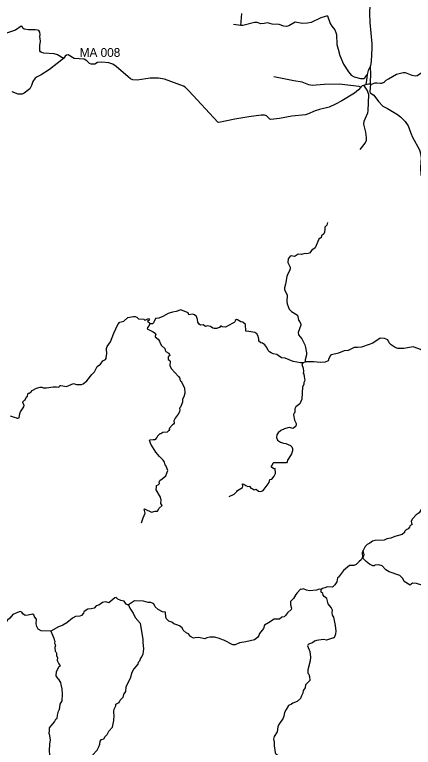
# Model space of a CAD drawing. Extents: x 332 to 501, y 9447 to 9559.
# Drawn here: x 458.02 to 475.23, y 9479.97 to 9511.64 of the extents above; entities that cross this region are included whole.
import ezdxf

# ---------------------------------------------------------------- set-up
doc = ezdxf.new("R2010")
doc.units = 0
for name, color, linetype in [('Level 31', 7, 'Continuous'), ('Level 4', 7, 'Continuous'), ('Level 5', 7, 'Continuous'), ('Level 6', 7, 'Continuous'), ('Level 7', 7, 'Continuous'), ('Level 8', 7, 'Continuous')]:
    doc.layers.add(name, color=color, linetype=linetype)

msp = doc.modelspace()

# ---------------------------------------------------------------- linework, layer by layer
at = {"layer": 'Level 4'}
for points in [[(473.3815, 9512.9204), (473.3415, 9511.6756), (473.3582, 9511.3032)], [(473.3582, 9511.3032), (473.4387, 9510.3831)], [(473.4387, 9510.3831), (473.445, 9510.1938), (473.4148, 9509.636)], [(462.2592, 9509.5019), (462.0871, 9509.5596), (461.7829, 9509.5879), (461.5917, 9509.569), (461.4851, 9509.5084), (461.3204, 9509.4996), (461.2528, 9509.5324), (461.1354, 9509.6523), (461.0181, 9509.723), (460.594, 9509.752), (460.3265, 9509.906), (460.262, 9509.8946), (460.2055, 9509.8444)], [(473.4148, 9509.636), (473.3907, 9509.429)], [(467.5283, 9507.1277), (466.8391, 9506.9741), (466.7923, 9506.9924), (465.537, 9508.3514), (465.38, 9508.5076), (465.3055, 9508.5517), (464.4927, 9508.8496), (464.2264, 9508.9039), (463.8642, 9508.8912), (463.3101, 9508.8105), (463.1144, 9508.8218), (463.0261, 9508.8661), (462.915, 9508.9544), (462.4064, 9509.4037), (462.2592, 9509.5019)], [(473.3907, 9509.429), (473.2771, 9509.2289)], [(472.9707, 9508.5154), (472.8695, 9508.394), (472.6877, 9508.2489), (472.1475, 9507.9119), (471.8794, 9507.7667), (471.6035, 9507.648), (471.1826, 9507.5484), (470.9939, 9507.4853), (470.6646, 9507.3435)], [(473.0437, 9508.5744), (472.9707, 9508.5154)], [(473.355, 9508.3214), (473.3744, 9508.257), (473.5233, 9508.1598), (473.7252, 9507.8866), (473.9208, 9507.6878), (474.124, 9507.5913), (474.5461, 9507.3199)], [(470.6646, 9507.3435), (470.5736, 9507.3155), (469.989, 9507.2491), (469.4542, 9507.1558), (469.0831, 9507.1104), (469.0376, 9507.1243), (468.8912, 9507.2695), (468.8055, 9507.3022), (468.6672, 9507.2997), (468.1245, 9507.231), (467.5283, 9507.1277)], [(474.5461, 9507.3199), (474.6869, 9507.2208), (474.8763, 9507.0284), (475.005, 9506.8365), (475.1276, 9506.5158)], [(475.1276, 9506.5158), (475.1968, 9506.3519), (475.4947, 9505.794), (475.5502, 9505.6451), (475.5755, 9505.4482), (475.5452, 9505.0342), (475.557, 9504.6897)], [(465.7046, 9498.6925), (465.5401, 9498.6668), (465.5144, 9498.7491), (465.1957, 9498.8878), (464.9952, 9498.8159), (464.8359, 9498.7902), (464.6457, 9498.7285), (464.4195, 9498.5948), (464.243, 9498.5262)], [(464.243, 9498.5262), (464.0956, 9498.5126), (464.0134, 9498.3224)], [(465.7817, 9498.6668), (465.7046, 9498.6925)], [(465.8691, 9498.5897), (465.7817, 9498.6668)], [(465.9976, 9498.2556), (465.9308, 9498.3532), (465.9205, 9498.4612), (465.8691, 9498.5897)], [(463.8547, 9498.2938), (463.7599, 9498.3741)], [(464, 9498.309), (463.9723, 9498.2813), (463.8695, 9498.2813), (463.8547, 9498.2938)], [(464.0134, 9498.3224), (464, 9498.309)], [(466.0491, 9498.2247), (465.9976, 9498.2556)], [(466.1519, 9498.235), (466.0491, 9498.2247)], [(466.8646, 9498.12), (466.7327, 9498.0756), (466.6402, 9498.0756), (466.5734, 9498.0911), (466.4757, 9498.1579), (466.4089, 9498.1785), (466.3472, 9498.1887), (466.2547, 9498.1682), (466.1519, 9498.235)], [(468.0013, 9497.9625), (467.9821, 9498.2438), (467.8734, 9498.3526), (467.7796, 9498.3714), (467.6371, 9498.4577), (467.6034, 9498.4614), (467.5359, 9498.4239), (467.5246, 9498.3601), (467.4984, 9498.3376), (467.4346, 9498.3151), (467.1234, 9498.135), (466.9846, 9498.1426), (466.9396, 9498.1801), (466.9021, 9498.1801), (466.8935, 9498.1672)], [(466.8935, 9498.1672), (466.8646, 9498.12)], [(469.0907, 9497.031), (469.026, 9497.0634), (468.9585, 9497.1309), (468.9135, 9497.2584), (468.8197, 9497.3784), (468.7185, 9497.4496), (468.651, 9497.4609), (468.561, 9497.5284), (468.561, 9497.6221), (468.531, 9497.7534), (468.4808, 9497.8425), (468.3871, 9497.8987), (468.1358, 9497.955), (468.0013, 9497.9625)], [(475.9999, 9496.9153), (475.8325, 9496.9871), (475.5416, 9497.175), (475.2766, 9497.2707), (475.2213, 9497.2781), (474.8211, 9497.2098), (474.5634, 9497.2098), (474.453, 9497.254), (474.2763, 9497.3718), (474.1916, 9497.4639), (474.129, 9497.5818), (473.9965, 9497.6518), (473.8087, 9497.6665), (473.4811, 9497.4455), (473.3319, 9497.3866), (472.9896, 9497.2761), (472.8165, 9497.254), (472.6803, 9497.2577), (472.4226, 9497.125), (472.2496, 9497.1066), (471.9999, 9497.0062)], [(469.1797, 9496.9884), (469.0907, 9497.031)], [(469.3425, 9496.961), (469.1797, 9496.9884)], [(469.4, 9496.9035), (469.3425, 9496.961)], [(471.9999, 9497.0062), (471.7047, 9496.9372), (471.6605, 9496.9077), (471.5869, 9496.7825), (471.5565, 9496.684)], [(469.5396, 9496.8131), (469.4, 9496.9035)], [(470.46, 9496.5995), (470.3607, 9496.5995), (470.0491, 9496.6488), (469.6958, 9496.7967), (469.5396, 9496.8131)], [(470.5662, 9496.6271), (470.46, 9496.5995)], [(470.5829, 9496.6314), (470.5662, 9496.6271)], [(471.5565, 9496.684), (471.4325, 9496.6251), (471.229, 9496.6065), (470.9366, 9496.6324), (470.5829, 9496.6314)]]:
    msp.add_lwpolyline(points, dxfattribs=at)
at = {"layer": 'Level 5'}
for points in [[(474.888, 9509.1414), (475.1766, 9509.0213), (475.3212, 9509.0005), (475.4064, 9509.0187), (475.7749, 9509.2648), (475.8733, 9509.3482), (476.1712, 9509.6612), (476.2267, 9509.7483), (476.2886, 9509.7962), (476.4515, 9509.8555), (476.7821, 9509.8908), (476.9537, 9509.9754), (477.1493, 9510.1534), (477.4169, 9510.515), (477.4926, 9510.5844), (477.7609, 9510.6771), (477.9596, 9510.8167), (478.2455, 9511.0621), (478.3169, 9511.0937)], [(460.1202, 9509.7546), (460.0539, 9509.6848), (459.5175, 9509.2754), (459.1645, 9509.0426), (458.9889, 9508.9622), (458.9061, 9508.9029), (458.7984, 9508.7529), (458.7515, 9508.5757), (458.6781, 9508.4305), (458.4236, 9508.2431), (458.3377, 9508.2033), (458.1691, 9508.2095), (457.9068, 9508.3055)], [(460.2055, 9509.8444), (460.1202, 9509.7546)], [(474.0631, 9508.804), (474.1581, 9508.8717), (474.5078, 9509.0654), (474.7949, 9509.1412), (474.888, 9509.1414)], [(473.8211, 9508.6842), (473.8794, 9508.685)], [(473.8794, 9508.685), (473.9382, 9508.7062)], [(473.9382, 9508.7062), (473.94, 9508.7071)], [(473.94, 9508.7071), (473.9856, 9508.7305)], [(473.9856, 9508.7305), (473.9914, 9508.735)], [(473.9914, 9508.735), (474.0538, 9508.7974)], [(474.0538, 9508.7974), (474.0631, 9508.804)], [(471.5245, 9502.6652), (471.5193, 9502.599)], [(471.5193, 9502.599), (471.4983, 9502.5472), (471.4097, 9502.463), (471.4145, 9502.3723), (471.3949, 9502.246), (471.3687, 9502.1712), (471.27, 9502.09), (471.2527, 9502.0052)], [(471.2527, 9502.0052), (471.1504, 9501.9357), (471.0017, 9501.5639), (470.8572, 9501.4601), (470.7549, 9501.3302), (470.6293, 9501.31), (470.5424, 9501.3159), (470.4103, 9501.2779), (470.2616, 9501.2974), (470.1384, 9501.2036), (470.0878, 9501.187), (469.9771, 9501.2137), (469.9176, 9501.2071), (469.8284, 9501.092), (469.8178, 9500.9331), (469.9226, 9500.7215), (469.919, 9500.6574), (469.8893, 9500.5714), (469.8233, 9500.4629), (469.7769, 9500.3229), (469.7151, 9499.9879), (469.667, 9499.8408), (469.6718, 9499.7637), (469.7879, 9499.5141), (469.7767, 9499.2449), (469.7916, 9499.1406), (469.8762, 9498.9087), (469.9727, 9498.8056), (470.2381, 9498.6468), (470.2775, 9498.4369), (470.3376, 9498.3657), (470.374, 9498.2679), (470.3751, 9498.2223), (470.2676, 9497.9014), (470.2688, 9497.8036), (470.423, 9497.6269), (470.5451, 9497.3661), (470.5719, 9497.2629), (470.6243, 9497.0204), (470.6196, 9496.9439), (470.5572, 9496.7186), (470.5614, 9496.6527)], [(461.9876, 9496.9343), (462.0042, 9496.9705), (461.9887, 9497.2136), (462.0071, 9497.305), (462.1551, 9497.5001), (462.296, 9497.8773), (462.475, 9498.2468), (462.5606, 9498.3518), (462.7349, 9498.3982), (462.8997, 9498.553), (463.1478, 9498.6023), (463.2151, 9498.5994), (463.3008, 9498.5621), (463.3728, 9498.4993), (463.6007, 9498.4739), (463.64, 9498.4436), (463.6763, 9498.4454), (463.7995, 9498.5048), (463.8346, 9498.4473), (463.7599, 9498.3741)], [(463.8547, 9498.2938), (463.8283, 9498.2093), (463.7615, 9498.1219), (463.7461, 9498.0602), (464, 9497.9287)], [(464, 9497.9287), (464.1008, 9497.8597), (464.1213, 9497.8289), (464.0802, 9497.7518), (464.0854, 9497.7158), (464.2087, 9497.6233), (464.2704, 9497.5307), (464.2807, 9497.4691), (464.3527, 9497.3457), (464.4966, 9497.212), (464.512, 9497.1349), (464.5429, 9497.0887), (464.6765, 9497.0064), (464.7125, 9496.9139), (464.6508, 9496.8522), (464.6508, 9496.7442), (464.7177, 9496.698), (464.7382, 9496.6494), (464.7228, 9496.4849), (464.7742, 9496.346), (465.0928, 9496)], [(461.8312, 9496.6745), (461.9413, 9496.7422), (461.9722, 9496.7831), (461.9876, 9496.9343)], [(458.1563, 9494.1973), (458.2187, 9494.2137), (458.2364, 9494.4052), (458.2655, 9494.4704), (458.4184, 9494.6929), (458.4219, 9494.7634), (458.3689, 9494.8583), (458.3701, 9494.9034), (458.4373, 9494.974), (458.4605, 9494.9728), (458.5348, 9495.1187), (458.577, 9495.1324), (458.5865, 9495.2593), (458.6097, 9495.2866), (458.643, 9495.2842), (458.7257, 9495.3346), (458.7768, 9495.4041), (458.9565, 9495.4972), (459.1153, 9495.5459), (459.1903, 9495.5448), (459.254, 9495.5128), (459.3962, 9495.5075), (459.6836, 9495.5551), (459.8306, 9495.5599), (459.9026, 9495.5463), (459.9335, 9495.5624), (459.9686, 9495.6122), (460.0186, 9495.6199), (460.2501, 9495.5673), (460.56, 9495.7044), (460.685, 9495.6511), (460.904, 9495.6577), (460.9754, 9495.6892), (461.133, 9495.8168), (461.3483, 9496.0908), (461.4673, 9496.1988), (461.579, 9496.4402), (461.7277, 9496.534), (461.8312, 9496.6745)], [(470.5614, 9496.6527), (470.5662, 9496.6271)], [(465.0928, 9496), (465.1546, 9495.9244), (465.1443, 9495.8781), (465.1752, 9495.8164), (465.2163, 9495.7804), (465.2317, 9495.7238), (465.3499, 9495.5078), (465.3602, 9495.2764), (465.3294, 9495.1222), (465.2625, 9495.0215), (465.2677, 9494.8878), (465.1803, 9494.6821), (465.134, 9494.6307), (465.1443, 9494.5587), (465.134, 9494.4815), (465.0844, 9494.3794)], [(470.5134, 9496), (470.5514, 9495.8288), (470.5111, 9495.7431), (470.5027, 9495.6507), (470.4422, 9495.5532), (470.4187, 9495.0253), (470.3348, 9494.8278), (470.1551, 9494.6901), (470.1199, 9494.6027), (470.1215, 9494.4481), (470.0695, 9494.3967), (470.0594, 9494.353), (470.1081, 9494.1161), (470.1769, 9493.9758), (470.1769, 9493.917), (470.1534, 9493.8548), (470.0426, 9493.7607), (469.8797, 9493.7926), (469.8092, 9493.7792)], [(458.1151, 9494.2023), (458.0098, 9494.2242), (457.8385, 9494.2894)], [(458.1151, 9494.2023), (458.1563, 9494.1973)], [(465.0826, 9494.3735), (464.949, 9494.2055), (464.8976, 9494.0821), (464.9079, 9493.9895), (464.877, 9493.9381), (464.8307, 9493.9134), (464.6971, 9493.7592), (464.7022, 9493.718), (464.6765, 9493.6666), (464.5994, 9493.5946), (464.4195, 9493.5895), (464.3321, 9493.5226), (464.2807, 9493.5226), (464.1882, 9493.4301), (464.1573, 9493.3735), (464.0648, 9493.2706), (464, 9493.2643)], [(465.0844, 9494.3794), (465.0826, 9494.3735)], [(469.8092, 9493.7792), (469.6699, 9493.7456), (469.5188, 9493.6696), (469.3934, 9493.5703), (469.3464, 9493.4815), (469.3255, 9493.3614), (469.362, 9493.2569), (469.4926, 9493.1681), (469.6232, 9493.1211), (469.7329, 9493.1055), (469.9262, 9493.0271), (469.9889, 9492.9696), (470.0202, 9492.8965), (470.0098, 9492.7973), (469.968, 9492.6667), (469.8635, 9492.4682), (469.7956, 9492.3898), (469.7904, 9492.3167), (469.7538, 9492.2645), (469.1778, 9492.2784)], [(463.4959, 9489.6717), (463.56, 9489.8982), (463.6587, 9490.1005), (463.6116, 9490.2683), (463.6283, 9490.2795), (463.6556, 9490.2701), (463.9276, 9490.1439), (464.0793, 9490.1831), (464.1882, 9490.1819), (464.2625, 9490.3053), (464.3857, 9490.4329), (464.3285, 9490.5159), (464.3427, 9490.6611), (464.3129, 9490.7934), (464.1354, 9491.1099), (464.1372, 9491.2398), (464.149, 9491.2855), (464.221, 9491.3205), (464.2656, 9491.3745), (464.259, 9491.4521), (464.2816, 9491.512), (464.3917, 9491.5785), (464.5511, 9491.7096), (464.6272, 9491.9457), (464.5592, 9492.1312), (464.5116, 9492.1881), (464.4842, 9492.2978), (464.4324, 9492.3802), (464.2734, 9492.5397), (464.1198, 9492.7382), (463.8918, 9493.0738), (463.8477, 9493.2552)], [(467.2791, 9490.8184), (467.4938, 9490.9163), (467.6187, 9491.0308), (467.6366, 9491.0741), (467.8579, 9491.2117), (467.8703, 9491.258), (467.853, 9491.3612), (467.9149, 9491.3511), (467.9965, 9491.2859), (468.0833, 9491.2551), (468.1542, 9491.2587), (468.2107, 9491.1816), (468.2762, 9491.1627), (468.366, 9491.0999), (468.4416, 9491.129), (468.5547, 9491.0531), (468.6439, 9491.027), (468.7463, 9491.0727), (469.0068, 9491.4227), (469.0442, 9491.5496), (469.1299, 9491.5716), (469.2203, 9491.6914), (469.2779, 9491.8071), (469.2671, 9492.0205), (469.2106, 9492.0152), (469.1023, 9492.0887), (469.1053, 9492.1308), (469.1481, 9492.1788), (469.1778, 9492.2784)], [(471.2492, 9486.7935), (471.1678, 9486.8109), (471.0469, 9486.7685), (470.7446, 9486.7443), (470.6237, 9486.7685), (470.4846, 9486.829), (470.406, 9486.7927), (470.3576, 9486.8048), (470.2137, 9486.6573)], [(470.1398, 9486.5548), (470.0645, 9486.4114), (469.9369, 9486.2769), (469.9255, 9486.1402), (469.9802, 9485.9898), (469.962, 9485.9351), (469.8048, 9485.7814), (469.7159, 9485.6697), (469.6589, 9485.6195), (469.5518, 9485.6013), (469.4538, 9485.5123), (469.2314, 9485.5087), (468.9853, 9485.3491), (468.8098, 9485.2624), (468.7574, 9485.1074), (468.5842, 9484.8894), (468.5637, 9484.8096), (468.4999, 9484.7229), (468.3746, 9484.6272), (467.9999, 9484.5316)], [(470.1466, 9486.5677), (470.1398, 9486.5548)], [(470.2137, 9486.6573), (470.1466, 9486.5677)], [(471.7927, 9484.7119), (471.8259, 9484.7341), (471.8624, 9484.7909), (471.8948, 9484.8842), (471.8988, 9485.0018), (471.8745, 9485.241), (471.8056, 9485.5978), (471.7488, 9485.6829), (471.7286, 9485.8005), (471.7367, 9485.91), (471.6921, 9486.0235), (471.5623, 9486.1736), (471.5015, 9486.4128), (471.388, 9486.4939), (471.3474, 9486.5507), (471.3271, 9486.6277), (471.2542, 9486.6845), (471.2492, 9486.7935)], [(462.9342, 9486.137), (462.8905, 9486.1293), (462.8272, 9486.1628), (462.7527, 9486.297), (462.5962, 9486.3193), (462.4769, 9486.3827), (462.395, 9486.4497), (462.3391, 9486.4348), (462.0894, 9486.2187), (461.9963, 9486.256), (461.9217, 9486.2597), (461.8137, 9486.2336), (461.6497, 9486.1218), (461.5305, 9486.0883), (461.4532, 9485.9883), (461.3265, 9485.9547), (461.1738, 9485.9398), (461.1067, 9485.91), (461.0061, 9485.8317), (460.9837, 9485.7758), (460.9055, 9485.6788), (460.831, 9485.6416), (460.6521, 9485.6266), (460.518, 9485.5633), (460.2653, 9485.3589), (460.0976, 9485.2508), (459.9999, 9485.2074)], [(464, 9486.1929), (463.8995, 9486.2328), (463.7833, 9486.2396), (463.5882, 9486.2989), (463.1985, 9486.308), (462.9342, 9486.137)], [(464.5367, 9485.8205), (464.4024, 9485.8387), (464.211, 9485.9322), (464.0886, 9486.0481), (464.0317, 9486.1803), (464, 9486.1929)], [(462.9342, 9486.137), (462.9889, 9485.9843), (463.1416, 9485.7745), (463.2259, 9485.5875), (463.4378, 9485.339), (463.5517, 9484.6363), (463.5472, 9484.5131), (463.5859, 9484.2372), (463.5579, 9484)], [(459.577, 9484.9926), (459.1633, 9485.0085), (459.0292, 9485.0868), (458.9733, 9485.1986), (458.9509, 9485.3067), (458.9547, 9485.5155), (458.869, 9485.6087), (458.8615, 9485.687), (458.7907, 9485.7318), (458.5976, 9485.6833), (458.4746, 9485.6758), (458.3666, 9485.743), (458.3331, 9485.8138), (458.2623, 9485.8399), (458.2138, 9485.8362), (457.9428, 9485.7169), (457.8049, 9485.5528), (457.6969, 9485.4521), (457.6261, 9485.3403)], [(465.6047, 9484.7617), (465.5295, 9484.8825), (465.4224, 9484.9213), (465.3016, 9485.0399), (465.2447, 9485.1334), (465.1337, 9485.2239), (465.0243, 9485.2764), (464.8967, 9485.306), (464.801, 9485.3858), (464.6802, 9485.4269), (464.5708, 9485.5249), (464.5458, 9485.6024), (464.5367, 9485.8205)], [(459.9999, 9485.2074), (459.9076, 9485.18), (459.577, 9484.9926)], [(467.9999, 9484.5316), (467.7286, 9484.4904), (467.544, 9484.4106), (467.4346, 9484.406), (467.0458, 9484.6135), (466.9866, 9484.6181), (466.8567, 9484.6751), (466.6448, 9484.7389), (466.4472, 9484.7389), (466.3173, 9484.7093), (466.2261, 9484.6682), (465.9573, 9484.7252), (465.8189, 9484.7115), (465.7392, 9484.6865), (465.6047, 9484.7617)], [(471.7927, 9484.7119), (471.4905, 9484.6009), (471.3607, 9484.6364), (471.0502, 9484.5972), (470.9687, 9484.5669), (470.8753, 9484.4951), (470.7492, 9484.4506), (470.6986, 9484.4162), (470.6635, 9484.3616), (470.7648, 9484.1239), (470.7988, 9483.8665), (470.781, 9483.7165), (470.6717, 9483.328), (470.6824, 9483.1846), (470.7235, 9483.1371), (470.7569, 9483.0411), (470.7581, 9482.859), (470.5833, 9482.6757), (470.5643, 9482.5524), (470.481, 9482.4367), (470.4638, 9482.3134), (470.4002, 9482.2048), (470.3598, 9482.0904)], [(463.5579, 9484), (463.5107, 9483.8947), (463.4538, 9483.8355), (463.4105, 9483.7032), (463.3489, 9483.6439), (463.333, 9483.5739), (463.1575, 9483.3687), (463.0755, 9483.216), (463.0071, 9482.9492), (462.818, 9482.5946), (462.8066, 9482.3917), (462.7291, 9482.2845), (462.7229, 9482.2535)], [(461.6568, 9480), (461.7014, 9480.1163), (461.7074, 9480.2421), (461.7733, 9480.3079), (461.8691, 9480.3379), (461.923, 9480.4397), (462.0128, 9480.5355), (462.0787, 9480.6732), (462.2463, 9480.8528), (462.3062, 9481.1342), (462.3182, 9481.3618), (462.2942, 9481.4516), (462.3002, 9481.5354), (462.3182, 9481.6312), (462.3901, 9481.763), (462.3841, 9481.8408), (462.5338, 9481.9186), (462.5697, 9482.0204), (462.6954, 9482.1282)], [(462.7229, 9482.2535), (462.6954, 9482.1282)], [(470.3598, 9482.0904), (470.2117, 9481.9587)], [(470.2117, 9481.9587), (470.035, 9481.8881), (469.9678, 9481.837), (469.8453, 9481.7783), (469.7388, 9481.6158), (469.6699, 9481.477), (469.6408, 9481.3204), (469.6081, 9481.238), (469.4327, 9480.9616), (469.3834, 9480.8578)], [(469.3834, 9480.8578), (469.3543, 9480.6479), (469.2306, 9480.445), (469.1926, 9480.3229), (469.2254, 9480.2055), (469.2213, 9480.0412), (469.2684, 9479.7459), (469.2868, 9479.7038), (469.3232, 9479.6695), (469.3886, 9479.647), (469.4184, 9479.6001), (469.3702, 9479.4578), (469.281, 9479.3433), (469.1633, 9479.1333), (468.9815, 9478.5806), (468.9043, 9478.1868), (468.8383, 9478.1323), (468.7991, 9478.0137), (468.705, 9477.9519)], [(461.1212, 9478.0194), (461.0513, 9478.8948), (461.2467, 9479.3637), (461.3422, 9479.5295), (461.3661, 9479.6253), (461.5877, 9479.8469), (461.6568, 9480)]]:
    msp.add_lwpolyline(points, dxfattribs=at)
at = {"layer": 'Level 6'}
for points in [[(467.7792, 9511.1807), (467.8298, 9511.6962)], [(471.5317, 9511.5985), (471.236, 9511.5072), (470.8281, 9511.3048), (470.6614, 9511.2691), (470.439, 9511.2553), (470.1283, 9511.313), (469.8515, 9511.1661), (469.7592, 9511.1364), (469.648, 9511.1473), (469.4356, 9511.2129), (469.1359, 9511.2259), (468.9394, 9511.2855), (468.7975, 9511.2538)], [(471.5317, 9511.5985), (471.6469, 9511.2531), (471.7084, 9511.1509), (471.8405, 9510.9921), (471.8921, 9510.877), (471.9189, 9510.7798), (471.9358, 9510.3501), (471.9813, 9510.1549)], [(467.7792, 9511.1807), (467.4735, 9511.2211)], [(468.7975, 9511.2538), (468.6516, 9511.2529), (468.4898, 9511.3016), (468.3786, 9511.2977), (467.8755, 9511.1777), (467.7792, 9511.1807)], [(471.9813, 9510.1549), (472.0599, 9509.8837), (472.2167, 9509.5037), (472.4311, 9509.1746), (472.5502, 9509.0276), (472.6812, 9508.9521), (472.9473, 9508.8846), (473.0902, 9508.8846), (473.1458, 9508.9062), (473.1945, 9509.0065), (473.2402, 9509.0563)], [(470.081, 9508.7835), (469.2114, 9508.9555)], [(470.724, 9508.6044), (470.4303, 9508.7216), (470.081, 9508.7835)], [(472.9707, 9508.5154), (472.8946, 9508.5417), (472.0292, 9508.6351), (471.3781, 9508.6192), (470.8669, 9508.5775), (470.724, 9508.6044)], [(472.9345, 9505.8183), (473.1543, 9506.0836), (473.2069, 9506.2137), (473.2158, 9506.3329), (473.181, 9506.5663), (473.0986, 9506.9059), (473.1155, 9507.037), (473.2703, 9507.3966), (473.2872, 9507.491), (473.318, 9508.1851), (473.2377, 9508.3818), (473.0901, 9508.5912)], [(470.46, 9496.5995), (470.4232, 9496.5287), (470.4741, 9496.36), (470.4893, 9496.224), (470.4758, 9496.1468), (470.5027, 9496.1048), (470.5134, 9496)], [(464, 9493.2643), (463.8477, 9493.2552)], [(475.9999, 9490.9149), (475.9622, 9490.9102), (475.9, 9490.809), (475.8455, 9490.7), (475.8377, 9490.6221), (475.791, 9490.4898), (475.6743, 9490.3496), (475.6276, 9490.2406), (475.5731, 9490.2562), (475.4797, 9490.1161), (475.3552, 9490.0226), (475.1917, 9489.8513), (475.145, 9489.7501), (475.1528, 9489.6597), (475.1839, 9489.6052), (475.0828, 9489.5507), (475.0672, 9489.4884), (475.0049, 9489.4261), (474.9271, 9489.3794), (474.8571, 9489.3016)], [(474.4342, 9489.0894), (474.2577, 9489.0225), (474.092, 9488.9876), (473.9743, 9488.9353), (473.5688, 9488.9124), (473.4641, 9488.8862), (473.3508, 9488.799), (473.2374, 9488.7467), (473.1502, 9488.6595), (473.0622, 9488.4886)], [(474.8571, 9489.3016), (474.8571, 9489.2626), (474.7481, 9489.177), (474.4342, 9489.0894)], [(473.0622, 9488.4886), (473.0194, 9488.3892), (473.0456, 9488.1887), (472.9758, 9488.084), (472.8907, 9488)], [(473.2016, 9488), (473.078, 9488.1178), (473.0743, 9488.18), (473.1109, 9488.3154), (473.0622, 9488.4886)], [(472.8907, 9488), (472.7665, 9487.8835), (472.6619, 9487.8312), (472.4787, 9487.8312), (472.2259, 9487.6132), (471.9999, 9487.3353)], [(475.919, 9486.9466), (475.6686, 9487.0504), (475.5991, 9486.9846), (475.3651, 9487.0614), (475.2005, 9487.0651), (475.1384, 9487.0321), (475.0981, 9486.9882), (474.8458, 9487.1492), (474.7873, 9487.2663), (474.6557, 9487.4017), (474.185, 9487.5653), (474.0533, 9487.6495), (473.8815, 9487.8141), (473.7462, 9487.8617), (473.5889, 9487.8434), (473.5377, 9487.8214), (473.4902, 9487.8251), (473.3412, 9487.8983), (473.2016, 9488)], [(471.9999, 9487.3353), (471.9643, 9487.2993), (471.9294, 9487.1336), (471.8509, 9486.9941), (471.7462, 9486.8982), (471.5282, 9486.9069), (471.4149, 9486.8633), (471.319, 9486.8458), (471.2492, 9486.7935)], [(459.577, 9484.9926), (459.7151, 9484.6953), (459.7189, 9484.628), (459.7488, 9484.5644), (459.7451, 9484.4821), (459.7787, 9484.3961), (459.7488, 9484.2951), (459.7638, 9484.138), (459.7974, 9484.1081), (459.8274, 9484.0482), (459.8274, 9483.9435), (459.8722, 9483.85), (459.8498, 9483.7378), (459.861, 9483.7004), (459.9209, 9483.5807), (459.9545, 9483.547)], [(459.8984, 9482.9387), (459.8057, 9483.0706), (459.8252, 9483.2524), (459.9329, 9483.4734), (459.9902, 9483.4972)], [(459.9545, 9483.547), (459.9902, 9483.4972)], [(459.8984, 9482.9387), (459.9957, 9482.7703), (460.0181, 9482.6955), (460.0555, 9482.5009), (460.0705, 9482.2764), (460.0555, 9481.9899), (459.962, 9481.8402), (459.9433, 9481.6007)], [(459.554, 9479.4767), (459.5219, 9479.8254), (459.535, 9480.1268), (459.5677, 9480.2906), (459.5415, 9480.4806), (459.5022, 9480.5789), (459.5284, 9480.7034), (459.5153, 9480.8148), (459.7314, 9481.0835), (459.7904, 9481.1883), (459.8493, 9481.2211), (459.8624, 9481.3587), (459.9083, 9481.5356)], [(459.9083, 9481.5356), (459.9433, 9481.6007)]]:
    msp.add_lwpolyline(points, dxfattribs=at)
at = {"layer": 'Level 7'}
msp.add_lwpolyline([(460.1202, 9509.7546), (459.8663, 9509.9093), (459.7244, 9509.956), (459.2818, 9509.9778), (459.1696, 9510.0116), (459.1339, 9510.0374), (459.1031, 9510.0791), (459.1031, 9510.3045), (459.1358, 9510.4992), (459.1011, 9510.6918), (459.115, 9510.7683), (459.107, 9510.8804), (459.0604, 9510.9549), (459.0108, 9510.9767), (458.9095, 9510.9936), (458.6107, 9510.9806), (458.4301, 9511.0153), (458.3735, 9511.061), (458.3477, 9511.1255), (458.2991, 9511.1434), (458.0579, 9510.9667), (457.6222, 9510.8346)], dxfattribs=at)
at = {"layer": 'Level 8'}
for points in [[(473.3942, 9509.0244), (473.3907, 9509.429)], [(473.2402, 9509.0563), (473.2112, 9508.8088)], [(473.2771, 9509.2289), (473.2402, 9509.0563)], [(473.3842, 9508.7751), (473.3942, 9509.0244)], [(473.2112, 9508.8088), (473.19, 9508.6275)], [(473.19, 9508.6275), (473.3005, 9508.6578), (473.3794, 9508.6546)], [(473.3794, 9508.6546), (473.3842, 9508.7751)], [(473.3794, 9508.6413), (473.4274, 9508.6376), (473.5889, 9508.6931), (473.652, 9508.6994)], [(473.3794, 9508.6546), (473.3794, 9508.6413)], [(473.652, 9508.6994), (473.8211, 9508.6842)], [(473.0437, 9508.5744), (473.0901, 9508.5912)], [(473.0901, 9508.5912), (473.19, 9508.6275)], [(473.3794, 9508.6413), (473.355, 9508.3214)]]:
    msp.add_lwpolyline(points, dxfattribs=at)

# ---------------------------------------------------------------- texts
at = {"layer": 'Level 31'}
msp.add_text('MA 008', height=0.38, dxfattribs=at).set_placement((460.8272, 9509.8182))

doc.saveas('drawing.dxf')
